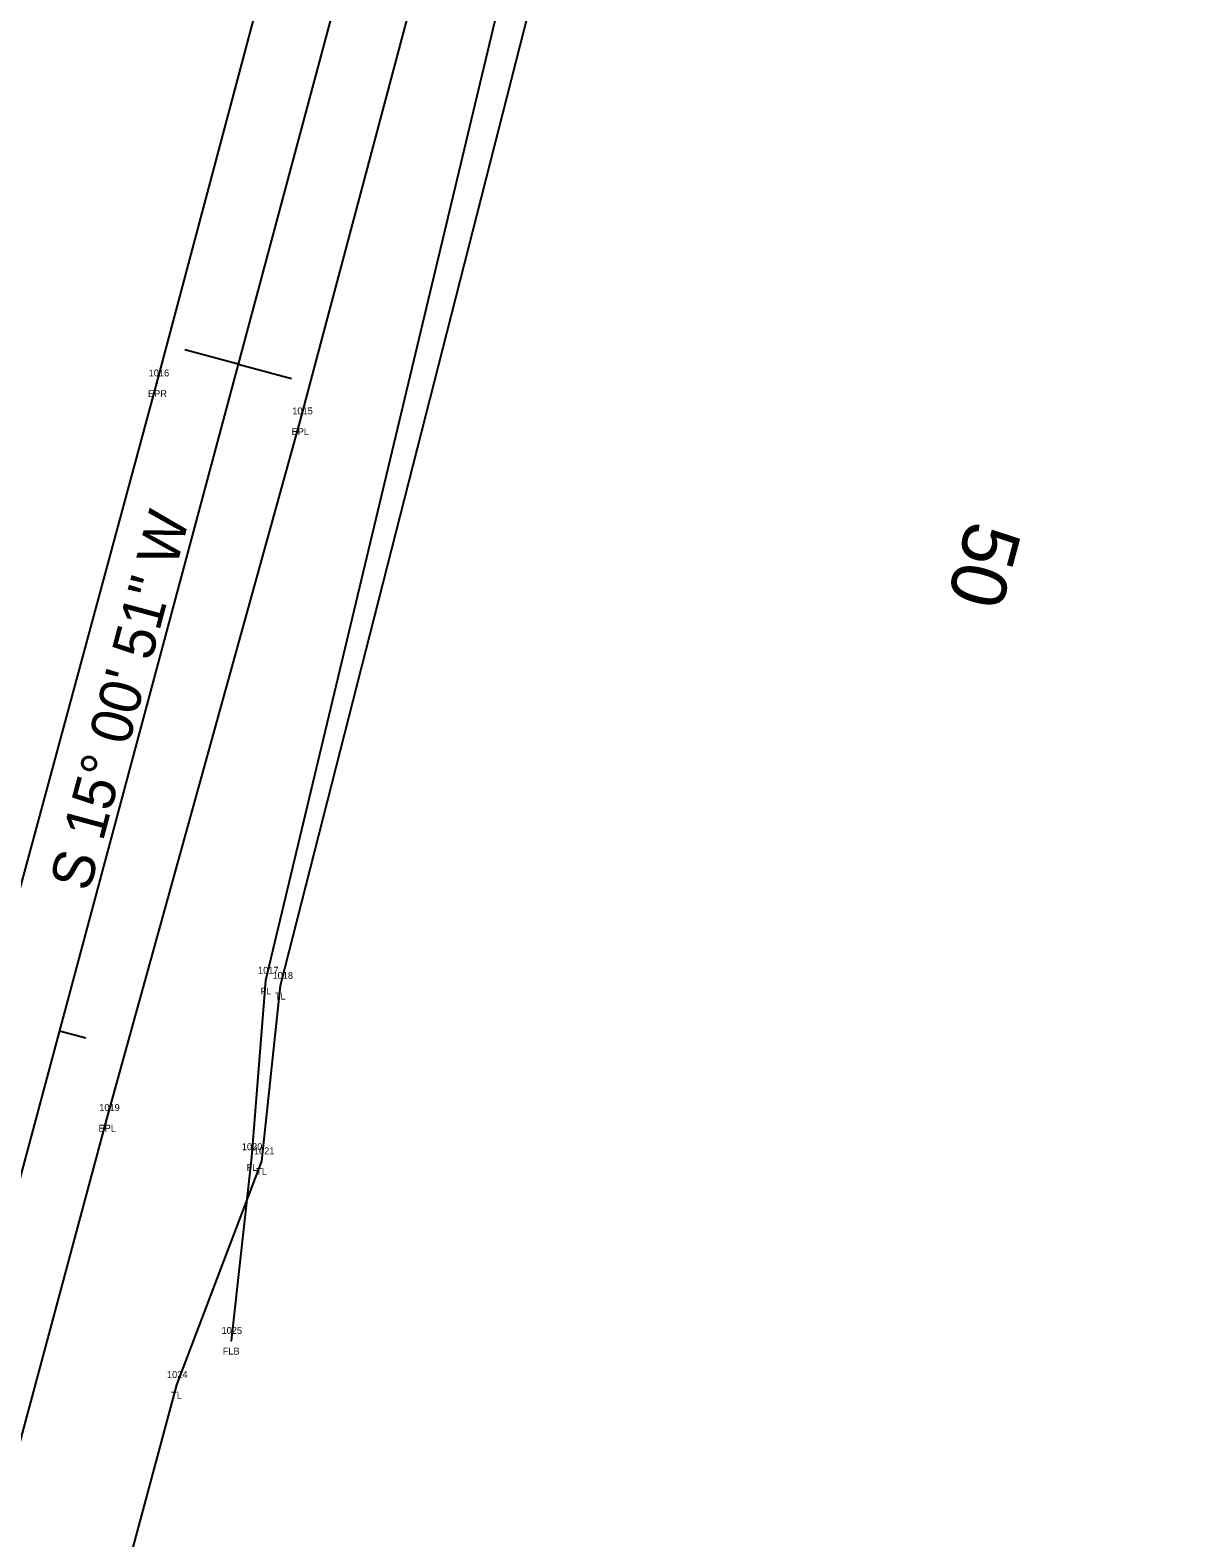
# Model space of a CAD drawing. Extents: x 2432632 to 2433497, y 684847 to 688233.
# Drawn here: x 2433031.5 to 2433197.4, y 687623.5 to 687841.9 of the extents above; entities that cross this region are included whole.
import ezdxf

# ---------------------------------------------------------------- set-up
doc = ezdxf.new("R2010")
doc.units = 0
for name, color, linetype in [('RD_EX_Fence_Other', 7, 'Continuous'), ('RD_EX_Fence_Other_txCode', 7, 'Continuous'), ('RD_EX_Road', 7, 'Continuous'), ('RD_EX_Road_txCode', 7, 'Continuous'), ('RD_EX_VEG', 7, 'Continuous'), ('RD_EX_VEG_txCode', 7, 'Continuous'), ('RD_HC_Cl', 7, 'Continuous'), ('RD_HC_Data', 7, 'Continuous'), ('RD_HC_Data_Tic', 7, 'Continuous'), ('RD_HC_TX_Sta50', 7, 'Continuous'), ('RD_SMD_Locator', 7, 'Continuous')]:
    doc.layers.add(name, color=color, linetype=linetype)

msp = doc.modelspace()

# ---------------------------------------------------------------- linework, layer by layer
at = {"layer": 'RD_EX_Fence_Other'}
msp.add_lwpolyline([(2433163.32, 688082.84), (2433107.2, 687878.29), (2433065.65, 687704.2), (2433063.62, 687678.63), (2433060.64, 687652.01)], dxfattribs=at)
at = {"layer": 'RD_EX_Road'}
for points in [[(2433130.63, 688090.22), (2433103.18, 687988.73), (2433075.68, 687887.89), (2433049.83, 687790.75), (2433022.33, 687689.17), (2432994.76, 687586.82), (2432966.23, 687480.17), (2432943.15, 687390.42), (2432931.4, 687334.3), (2432921.83, 687273.88), (2432915.64, 687215.4), (2432913.86, 687159.12), (2432915.08, 687107.55), (2432919.97, 687053.4), (2432928.7, 686998.89), (2432946.77, 686924.59), (2432964.57, 686864), (2432997.3, 686766.34), (2433031.44, 686666.38), (2433066.06, 686565.78), (2433098.73, 686469.74)], [(2433151.11, 688085.43), (2433123.35, 687982.08), (2433096.36, 687882.07), (2433070.62, 687785.25), (2433042.64, 687684.31), (2433015.24, 687582.49), (2432986.34, 687474.01), (2432964, 687384.38)]]:
    msp.add_lwpolyline(points, dxfattribs=at)
at = {"layer": 'RD_EX_VEG'}
msp.add_lwpolyline([(2433166.25, 688082.87), (2433111.93, 687876.69), (2433067.75, 687703.46), (2433065.05, 687678.03), (2433052.74, 687645.62), (2433005.45, 687469.88), (2432979.96, 687326.61), (2432966.8, 687267.34), (2432959.05, 687210.65), (2432959.25, 687071.62), (2432974.82, 687014.37), (2432998.13, 686938.9), (2433012.99, 686878.7), (2433054.45, 686782.35), (2433123.54, 686586.06), (2433129.82, 686546.35), (2433158.34, 686434.26), (2433192.79, 686274.67), (2433189.42, 686162.6), (2433197.4, 686074.41)], dxfattribs=at)
at = {"layer": 'RD_HC_Cl'}
msp.add_line((2433140.58, 688087.72), (2432956.34, 687400.83), dxfattribs=at)
at = {"layer": 'RD_HC_Data_Tic'}
for p, q in [((2433061.67, 687793.52), (2433053.94, 687795.59)), ((2433061.67, 687793.52), (2433069.39, 687791.45)), ((2433035.76, 687696.93), (2433039.62, 687695.9))]:
    msp.add_line(p, q, dxfattribs=at)
at = {"layer": 'RD_SMD_Locator'}
for centre in [(2433049.83, 687790.75), (2433070.62, 687785.25), (2433065.65, 687704.2), (2433067.75, 687703.46), (2433042.64, 687684.31), (2433063.62, 687678.63), (2433065.05, 687678.03), (2433060.64, 687652.01), (2433052.74, 687645.62)]:
    msp.add_circle(centre, 0.001, dxfattribs=at)

# ---------------------------------------------------------------- texts
at = {"layer": 'RD_EX_Fence_Other_txCode'}
for s, p in [('1017', (2433064.55, 687705.2)), ('FL', (2433064.92, 687702.2)), ('1020', (2433062.2, 687679.63)), ('FL', (2433062.89, 687676.63)), ('1025', (2433059.26, 687653.01)), ('FLB', (2433059.44, 687650.01))]:
    msp.add_text(s, height=1, dxfattribs=at).set_placement(p)
at = {"layer": 'RD_EX_Road_txCode'}
for s, p in [('1016', (2433048.7, 687791.75)), ('EPR', (2433048.6, 687788.75)), ('1015', (2433069.51, 687786.25)), ('EPL', (2433069.41, 687783.25)), ('1019', (2433041.54, 687685.31)), ('EPL', (2433041.44, 687682.31))]:
    msp.add_text(s, height=1, dxfattribs=at).set_placement(p)
at = {"layer": 'RD_EX_VEG_txCode'}
for s, p in [('1018', (2433066.65, 687704.46)), ('TL', (2433066.98, 687701.46)), ('1021', (2433063.95, 687679.03)), ('TL', (2433064.28, 687676.03)), ('1024', (2433051.35, 687646.62)), ('TL', (2433051.97, 687643.62))]:
    msp.add_text(s, height=1, dxfattribs=at).set_placement(p)
at = {"layer": 'RD_HC_Data'}
msp.add_text('S 15%%d 00\' 51" W', height=6, rotation=74.9858, dxfattribs=at).set_placement((2433040.09, 687716.92))
at = {"layer": 'RD_HC_TX_Sta50'}
msp.add_text('50', height=8, rotation=254.9858, dxfattribs=at).set_placement((2433167.48, 687771.14))

doc.saveas('drawing.dxf')
